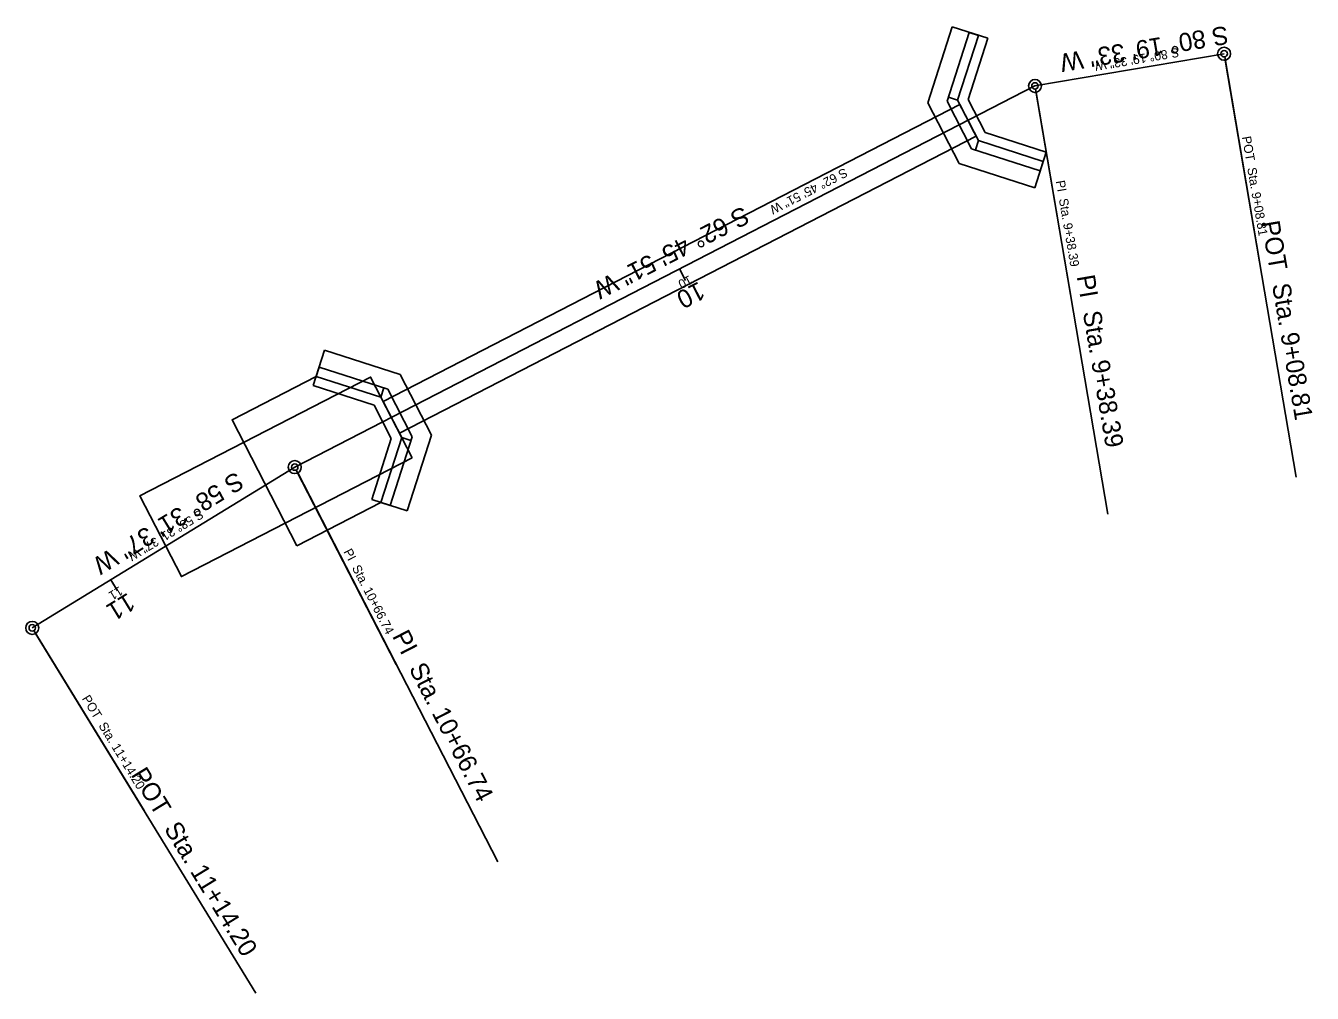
# Model space of a CAD drawing. Extents: x 1715692 to 1716581, y 394064 to 395904.
# Drawn here: x 1715955.9 to 1716154.3, y 394948.2 to 395097.3 of the extents above; entities that cross this region are included whole.
import ezdxf

# ---------------------------------------------------------------- set-up
doc = ezdxf.new("R2010")
doc.units = 0
for name, color, linetype in [('DR_P_Culvert', 7, 'Continuous'), ('DR_P_Headwall', 7, 'Continuous'), ('DR_P_Staging_Area', 7, 'Continuous'), ('GE_P_CL_10', 7, 'Continuous'), ('GE_P_CL_20', 7, 'Continuous'), ('SC_Scratch17', 7, 'Continuous')]:
    doc.layers.add(name, color=color, linetype=linetype)

msp = doc.modelspace()

# ---------------------------------------------------------------- linework, layer by layer
at = {"layer": 'DR_P_Culvert'}
msp.add_lwpolyline([(1716013.54, 395034.52), (1716011.02, 395039.41), (1716099.93, 395085.18), (1716102.45, 395080.29)], close=True, dxfattribs=at)
at = {"layer": 'DR_P_Headwall'}
for p, q in [((1716095, 395085.46), (1716098.74, 395097.14)), ((1716097.97, 395085.71), (1716101.36, 395096.3)), ((1716098.74, 395097.14), (1716104.22, 395095.39)), ((1716101.36, 395096.3), (1716102.79, 395095.84)), ((1716102.79, 395095.84), (1716099.59, 395085.84)), ((1716104.22, 395095.39), (1716101.21, 395085.98)), ((1716099.59, 395085.84), (1716098.16, 395086.3)), ((1716099.82, 395076.11), (1716095, 395085.46)), ((1716101.74, 395078.38), (1716097.97, 395085.71)), ((1716099.59, 395085.84), (1716102.79, 395079.62)), ((1716101.21, 395085.98), (1716103.84, 395080.86)), ((1716103.84, 395080.86), (1716113.25, 395077.85)), ((1716112.33, 395074.99), (1716101.74, 395078.38)), ((1716102.79, 395079.62), (1716102.33, 395078.19)), ((1716102.79, 395079.62), (1716112.79, 395076.42)), ((1716113.25, 395077.85), (1716111.49, 395072.37)), ((1716112.79, 395076.42), (1716112.33, 395074.99)), ((1716111.49, 395072.37), (1716099.82, 395076.11)), ((1716001.97, 395047.33), (1716000.22, 395041.86)), ((1716013.65, 395043.59), (1716001.97, 395047.33)), ((1716001.13, 395044.71), (1716000.68, 395043.28)), ((1716011.73, 395041.32), (1716001.13, 395044.71)), ((1716000.68, 395043.28), (1716010.68, 395040.08)), ((1716018.46, 395034.24), (1716013.65, 395043.59)), ((1716000.22, 395041.86), (1716009.63, 395038.84)), ((1716010.68, 395040.08), (1716011.13, 395041.51)), ((1716015.5, 395033.99), (1716011.73, 395041.32)), ((1716009.63, 395038.84), (1716012.26, 395033.72)), ((1716010.68, 395040.08), (1716013.88, 395033.86)), ((1716012.26, 395033.72), (1716009.25, 395024.31)), ((1716013.88, 395033.86), (1716010.68, 395023.86)), ((1716012.1, 395023.4), (1716015.5, 395033.99)), ((1716013.88, 395033.86), (1716015.31, 395033.4)), ((1716014.72, 395022.56), (1716018.46, 395034.24)), ((1716009.25, 395024.31), (1716014.72, 395022.56)), ((1716010.68, 395023.86), (1716012.1, 395023.4))]:
    msp.add_line(p, q, dxfattribs=at)
at = {"layer": 'DR_P_Staging_Area'}
msp.add_lwpolyline([(1716015.48, 395030.74), (1716009.07, 395043.19), (1715973.51, 395024.89), (1715979.92, 395012.44)], close=True, dxfattribs=at)
at = {"layer": 'GE_P_CL_10'}
for p, q in [((1716140.67, 395093.02), (1716111.51, 395088.05)), ((1716140.76, 395092.52), (1716146.23, 395060.4)), ((1716111.51, 395088.05), (1715997.39, 395029.31)), ((1716111.59, 395087.55), (1716117.14, 395055.04)), ((1716101.19, 395082.73), (1716101.65, 395081.84)), ((1716056.73, 395059.85), (1716057.19, 395058.96)), ((1716012.28, 395036.97), (1716012.73, 395036.08)), ((1715997.39, 395029.31), (1715956.92, 395004.53)), ((1715997.62, 395028.86), (1716013.04, 394998.89)), ((1715969.02, 395011.94), (1715969.55, 395011.09)), ((1715957.18, 395004.1), (1715974.15, 394976.37))]:
    msp.add_line(p, q, dxfattribs=at)
for centre in [(1716140.67, 395093.02), (1716111.51, 395088.05), (1715997.39, 395029.31), (1715956.92, 395004.53)]:
    msp.add_circle(centre, 0.5, dxfattribs=at)
at = {"layer": 'GE_P_CL_20'}
for p, q in [((1716140.67, 395093.02), (1716111.51, 395088.05)), ((1716140.84, 395092.03), (1716151.79, 395027.78)), ((1716111.51, 395088.05), (1715997.39, 395029.31)), ((1716111.68, 395087.06), (1716122.76, 395022.04)), ((1716101.19, 395082.73), (1716102.1, 395080.95)), ((1716056.73, 395059.85), (1716057.65, 395058.07)), ((1716012.28, 395036.97), (1716013.19, 395035.19)), ((1715997.39, 395029.31), (1715956.92, 395004.53)), ((1715997.85, 395028.42), (1716028.7, 394968.48)), ((1715969.02, 395011.94), (1715970.07, 395010.24)), ((1715957.44, 395003.68), (1715991.39, 394948.22))]:
    msp.add_line(p, q, dxfattribs=at)
for centre in [(1716140.67, 395093.02), (1716111.51, 395088.05), (1715997.39, 395029.31), (1715956.92, 395004.53)]:
    msp.add_circle(centre, 1, dxfattribs=at)
at = {"layer": 'SC_Scratch17'}
msp.add_lwpolyline([(1715997.72, 395017.19), (1716010.68, 395023.86), (1716013.88, 395033.86), (1716010.68, 395040.08), (1716000.68, 395043.28), (1715987.72, 395036.61)], close=True, dxfattribs=at)

# ---------------------------------------------------------------- texts
at = {"layer": 'GE_P_CL_10'}
for s, rotation, p in [('S 80%%d 19\' 33" W', 189.6742, (1716133.58, 395093.94)), ('POT  Sta. 9+08.81', 279.6742, (1716143.41, 395080.19)), ('S 62%%d 45\' 51" W', 207.2357, (1716082.14, 395075.45)), ('PI  Sta. 9+38.39', 279.6742, (1716114.72, 395073.38)), ('10', 207.2357, (1716058.21, 395058.92)), ('S 58%%d 31\' 37" W', 211.4731, (1715982.76, 395022.81)), ('PI  Sta. 10+66.74', 297.2357, (1716004.88, 395016.29)), ('11', 211.4731, (1715970.34, 395010.99)), ('POT  Sta. 11+14.20', 301.4731, (1715964.53, 394993.64))]:
    msp.add_text(s, height=1.4, rotation=rotation, dxfattribs=at).set_placement(p)
at = {"layer": 'GE_P_CL_20'}
for s, rotation, p in [('S 80%%d 19\' 33" W', 189.6742, (1716141.06, 395097.34)), ('S 62%%d 45\' 51" W', 207.2357, (1716066.5, 395069.6)), ('POT  Sta. 9+08.81', 279.6742, (1716146.41, 395067.06)), ('PI  Sta. 9+38.39', 279.6742, (1716117.93, 395058.71)), ('10', 207.2357, (1716059.68, 395057.99)), ('S 58%%d 31\' 37" W', 211.4731, (1715988.37, 395028.71)), ('11', 211.4731, (1715971.65, 395010.03)), ('PI  Sta. 10+66.74', 297.2357, (1716012.36, 395003.27)), ('POT  Sta. 11+14.20', 301.4731, (1715972.06, 394981.92))]:
    msp.add_text(s, height=2.8, rotation=rotation, dxfattribs=at).set_placement(p)

doc.saveas('drawing.dxf')
